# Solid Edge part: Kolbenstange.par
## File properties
Username: bmolnar
Dokumentum tartalom típus: 0
Author: bmolnar
Last saved by: bmolnar
Revision: 91
Sűrűség: 0,000 kg/m^3
Pontosság: 0,990
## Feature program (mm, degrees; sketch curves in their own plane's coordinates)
base feature "unnamed BaseFeature 1"
sketch for "unnamed Protrusion 1" plane through (62.5, 0, 0) normal (1, 0, 0) x-axis (0, 0, -1)
  circle centre (0, 0) radius 50
extrude "unnamed Protrusion 1" add finite 14 along +normal
thread "unnamed Thread 1"
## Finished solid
Body 1: solid body, 17 faces, 23 edges, 8 vertices.
  Faces by surface: plane 8, cylinder 4, torus 3, cone 2
  Edges by curve: circle 13, line 6, ellipse 2, intersection 2
Bounding box of the edges (mm; curved faces can reach further): 196.500 x 100.000 x 100.000, from (-120, -50, -50) to (76.5, 50, 50).
Cylindrical faces by radius (mm): R7 x1, R8 x1, R12.5 x1, R50 x1
Conical faces (half-angle, radius in mm at the cone's reference point): 20 deg R7.4 x1, 60 deg R7.6 x1
Toroidal faces (ring radius, tube radius in mm): R7.4 r0.4 x2, R10.7 r1.8 x1
Planar faces by outward normal: +x 1, +z 1, -x 3, -z 1, oblique 2
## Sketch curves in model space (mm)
circle centre (62.5, 0, 0) radius 50
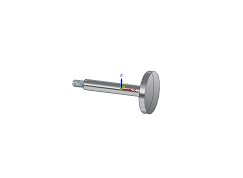
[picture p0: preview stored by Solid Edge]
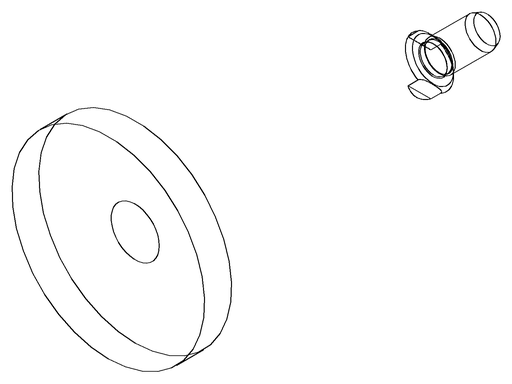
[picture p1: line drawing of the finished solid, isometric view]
